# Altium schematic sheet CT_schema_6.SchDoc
size 266 x 267 mm
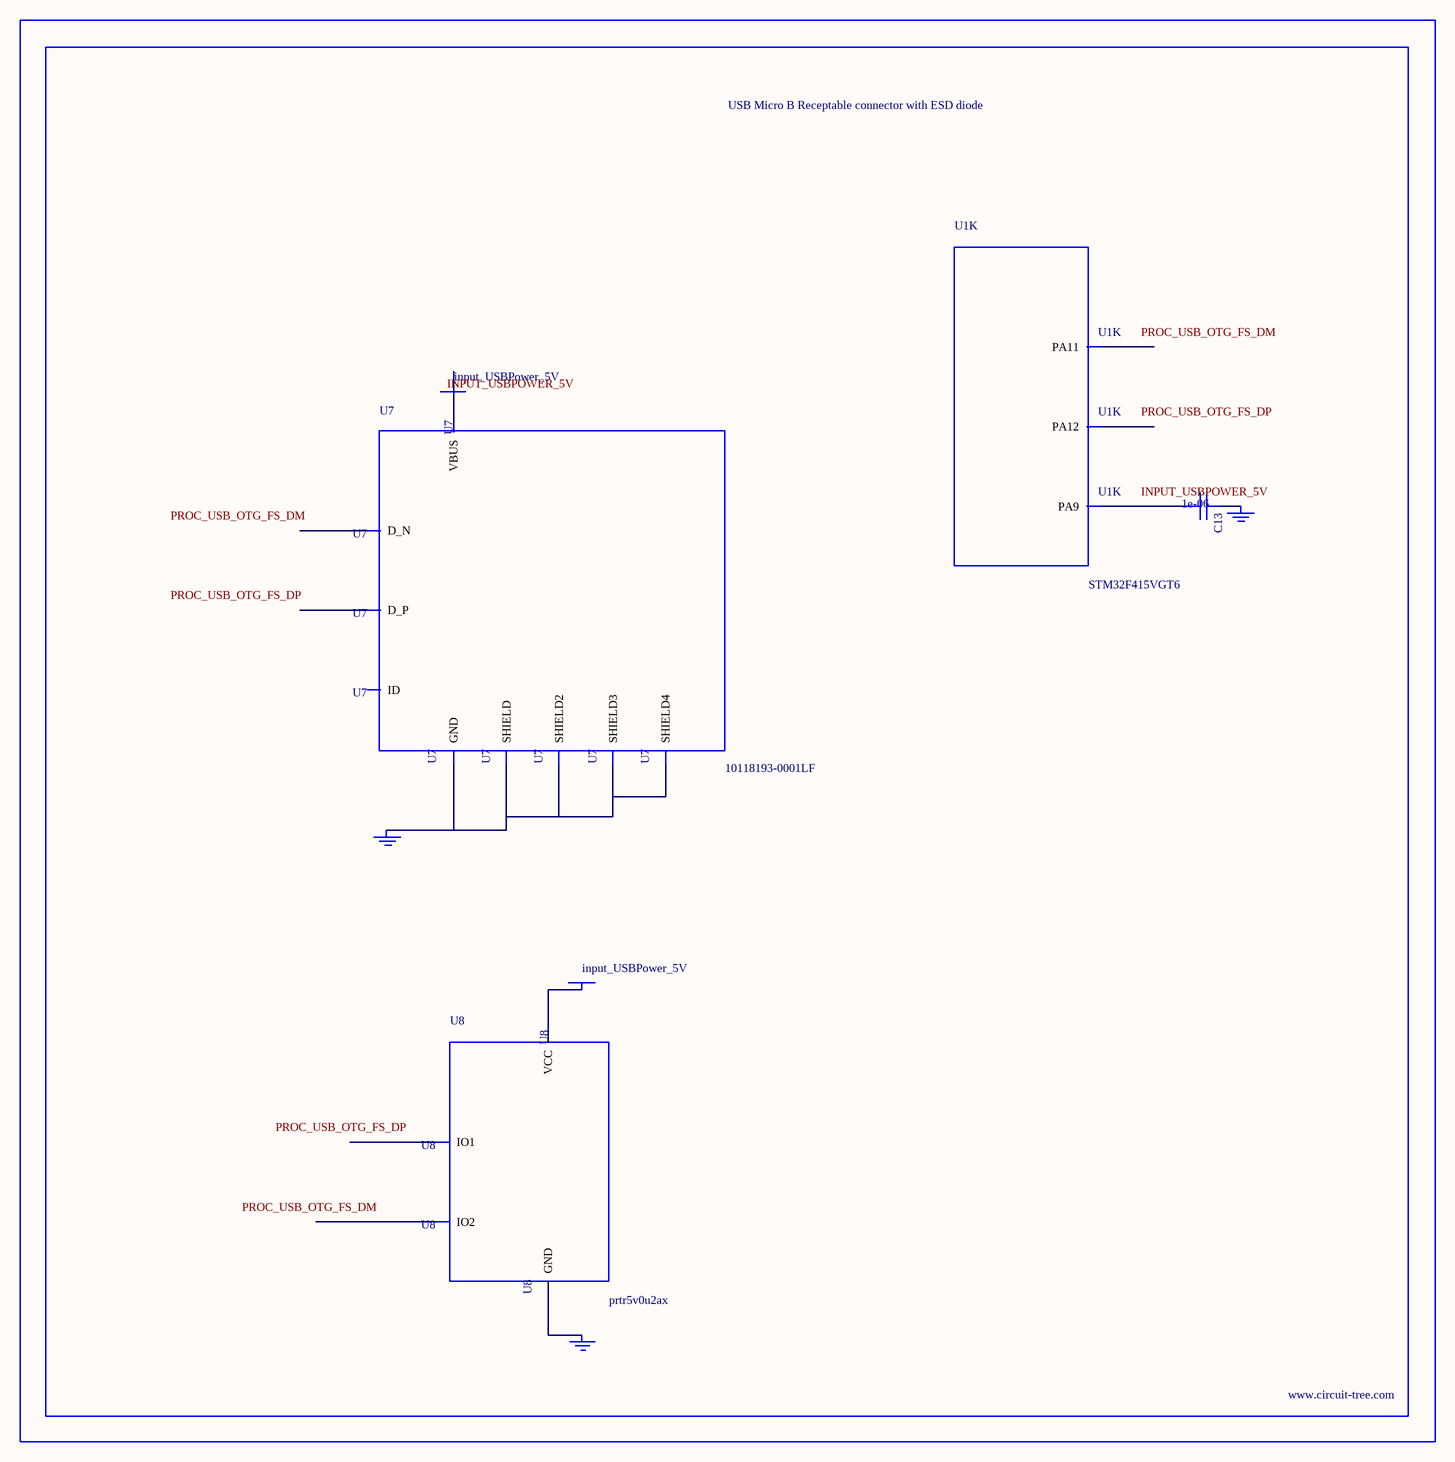
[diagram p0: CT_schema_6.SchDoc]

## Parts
BORDER5  (no value)
C13  1e-06  [C0603]
GND_INSTANCE_5_0  (no value)
GND_INSTANCE_5_1  (no value)
GND_INSTANCE_5_2  (no value)
POWER_INSTANCE_5_0  input_USBPower_5V
POWER_INSTANCE_5_1  input_USBPower_5V
U1  STM32F415VGT6  [LQFP100]  (part K of 11)
U7  10118193-0001LF  [FCI_10118193-0001LF]
U8  prtr5v0u2ax  [SOT143B]

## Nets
NetC13_1: C13.1 GND_INSTANCE_5_1.0(GND)
NetC13_2: C13.2 U1.68(PA9)
NetGND_INSTANCE_5_0_0: GND_INSTANCE_5_0.0(GND) U7.5(GND) U7.6(SHIELD) U7.7(SHIELD2) U7.8(SHIELD3) U7.9(SHIELD4)
NetGND_INSTANCE_5_2_0: GND_INSTANCE_5_2.0(GND) U8.1(GND)
NetPOWER_INSTANCE_5_0_0: POWER_INSTANCE_5_0.0(PWR) U7.1(VBUS)
NetPOWER_INSTANCE_5_1_0: POWER_INSTANCE_5_1.0(PWR) U8.4(VCC)

Not connected (* = marked no-connect by the designer): U1 70(PA11) 71(PA12); U7 2(D_N) 3(D_P) 4(ID); U8 2(IO1) 3(IO2)

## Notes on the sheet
- Labels drawn without touching a wire or pin: INPUT_USBPOWER_5V, PROC_USB_OTG_FS_DM, PROC_USB_OTG_FS_DP

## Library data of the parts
BORDER5 = BORDER_PAGE5
C13 = C0603C105K3RACTU
GND_INSTANCE_5_0-GND_INSTANCE_5_2 = GND
POWER_INSTANCE_5_0 POWER_INSTANCE_5_1 = PWR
